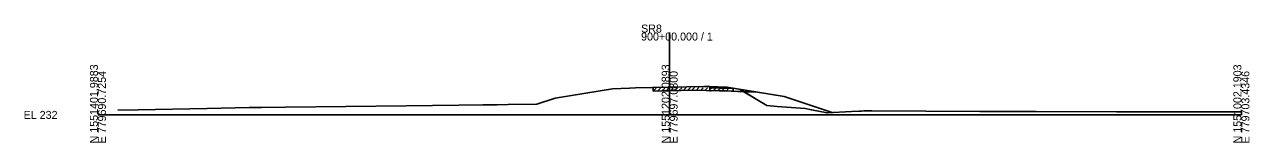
# Model space of a CAD drawing. Extents: x -26 to 787523, y -10 to 1545496.
# Drawn here: x -25.7 to 402.8, y 6490.3 to 6531.7 of the extents above; entities that cross this region are included whole.
import ezdxf

# ---------------------------------------------------------------- set-up
doc = ezdxf.new("R2010")
doc.units = 0
for name, color, linetype in [('50', 7, 'Continuous'), ('XS_CELL', 7, 'Continuous'), ('XS_M_SHAPES_EARTHWORK', 7, 'Continuous'), ('XS_P_FINISHED_GRADE', 7, 'Continuous'), ('XS_P_SUBGRADE_GRANULAR', 7, 'Continuous'), ('XS_X_GROUND', 7, 'Continuous')]:
    doc.layers.add(name, color=color, linetype=linetype)

msp = doc.modelspace()

# ---------------------------------------------------------------- linework, layer by layer
at = {"layer": '50'}
for p, q in [((197.23, 6508.39), (198.26, 6509.41)), ((198.73, 6508.42), (199.76, 6509.44)), ((200.24, 6508.45), (201.26, 6509.48)), ((201.74, 6508.49), (202.76, 6509.51)), ((203.24, 6508.52), (204.26, 6509.54)), ((204.74, 6508.55), (205.76, 6509.57)), ((206.24, 6508.58), (207.26, 6509.6)), ((207.74, 6508.61), (208.73, 6509.6)), ((209.24, 6508.59), (210.22, 6509.57)), ((210.74, 6508.56), (211.72, 6509.54)), ((212.25, 6508.53), (213.23, 6509.51)), ((213.75, 6508.5), (214.73, 6509.48)), ((215.25, 6508.47), (216.23, 6509.45)), ((216.75, 6508.44), (217.73, 6509.42)), ((194.23, 6508.33), (195.25, 6509.35)), ((194.23, 6508.33), (194.23, 6509.33)), ((194.23, 6508.33), (197.61, 6508.4)), ((195.73, 6508.36), (196.75, 6509.38)), ((197.61, 6508.4), (200, 6508.45)), ((200, 6508.45), (208.02, 6508.62)), ((208.02, 6508.62), (217.45, 6508.42)), ((217.45, 6508.42), (222.23, 6508.32)), ((218.25, 6508.4), (219.23, 6509.38)), ((219.75, 6508.37), (220.73, 6509.35)), ((222.23, 6509.32), (222.23, 6508.32))]:
    msp.add_line(p, q, dxfattribs=at)
at = {"layer": 'XS_CELL'}
for p, q in [((200, 6500), (200, 6528.86)), ((0, 6500), (200, 6500)), ((200, 6500), (400, 6500))]:
    msp.add_line(p, q, dxfattribs=at)
at = {"layer": 'XS_M_SHAPES_EARTHWORK'}
for points in [[(224.74, 6508.88), (226, 6508.12), (230.89, 6507.92), (220, 6509.74), (214, 6509.98), (214, 6509.49), (217.45, 6509.42), (222.23, 6509.32)], [(224.74, 6508.88), (226, 6508.12), (230.89, 6507.92), (220, 6509.74), (214, 6509.98), (214, 6509.49), (217.45, 6509.42), (222.23, 6509.32)], [(214, 6508.49), (214, 6509.49), (217.45, 6509.42), (222.23, 6509.32), (222.23, 6508.32), (219.51, 6508.38), (216, 6508.52), (214.37, 6508.49)], [(214, 6508.49), (214, 6509.49), (217.45, 6509.42), (222.23, 6509.32), (222.23, 6508.32), (219.51, 6508.38), (216, 6508.52), (214.37, 6508.49)], [(214, 6508.48), (214, 6508.49), (214.37, 6508.49)], [(214, 6508.48), (214, 6508.49), (214.37, 6508.49)], [(224.74, 6508.88), (226, 6508.12), (219.51, 6508.38), (222.23, 6508.32), (222.23, 6509.32)], [(224.74, 6508.88), (226, 6508.12), (219.51, 6508.38), (222.23, 6508.32), (222.23, 6509.32)], [(237.63, 6502.97), (247.38, 6502.27), (249.66, 6501.81), (255.07, 6500.69), (256.85, 6500.79), (240, 6506.4), (230.89, 6507.92), (226, 6508.12), (230.25, 6505.53), (234, 6503.24)], [(234, 6503.24), (237.63, 6502.97), (247.38, 6502.27), (249.66, 6501.81), (255.07, 6500.69), (256.85, 6500.79), (240, 6506.4), (230.89, 6507.92), (226, 6508.12), (230.25, 6505.53)]]:
    msp.add_lwpolyline(points, close=True, dxfattribs=at)
at = {"layer": 'XS_P_FINISHED_GRADE'}
for p, q in [((214, 6509.98), (220, 6509.74)), ((220, 6509.74), (240, 6506.4)), ((240, 6506.4), (256.85, 6500.79))]:
    msp.add_line(p, q, dxfattribs=at)
at = {"layer": 'XS_P_SUBGRADE_GRANULAR'}
for p, q in [((214, 6508.48), (214, 6509.98)), ((214, 6508.48), (216, 6508.52)), ((216, 6508.52), (230.89, 6507.92))]:
    msp.add_line(p, q, dxfattribs=at)
at = {"layer": 'XS_X_GROUND'}
for p, q in [((180, 6509.18), (186, 6509.42)), ((186, 6509.42), (188, 6509.46)), ((188, 6509.46), (200, 6509.7)), ((200, 6509.7), (212, 6509.94)), ((212, 6509.94), (214, 6509.98)), ((214, 6509.98), (214, 6509.49)), ((214, 6509.49), (217.45, 6509.42)), ((217.45, 6509.42), (222.23, 6509.32)), ((153.59, 6503.71), (160, 6505.84)), ((160, 6505.84), (180, 6509.18)), ((222.23, 6509.32), (224.74, 6508.88)), ((224.74, 6508.88), (230.25, 6505.53)), ((230.25, 6505.53), (234, 6503.24)), ((6.94, 6501.6), (14.05, 6501.75)), ((14.05, 6501.75), (38.21, 6502.25)), ((38.21, 6502.25), (52.95, 6502.55)), ((52.95, 6502.55), (57.27, 6502.64)), ((57.27, 6502.64), (65.6, 6502.72)), ((65.6, 6502.72), (107.77, 6503.12)), ((107.77, 6503.12), (126.22, 6503.36)), ((126.22, 6503.36), (134.7, 6503.47)), ((134.7, 6503.47), (137.11, 6503.5)), ((137.11, 6503.5), (138.26, 6503.51)), ((138.26, 6503.51), (138.92, 6503.52)), ((138.92, 6503.52), (139.36, 6503.53)), ((139.36, 6503.53), (139.67, 6503.53)), ((139.67, 6503.53), (143.52, 6503.6)), ((143.52, 6503.6), (153.59, 6503.71)), ((234, 6503.24), (237.63, 6502.97)), ((237.63, 6502.97), (247.38, 6502.27)), ((247.38, 6502.27), (249.66, 6501.81)), ((249.66, 6501.81), (255.07, 6500.69)), ((255.07, 6500.69), (263.65, 6501.16)), ((263.65, 6501.16), (266.22, 6501.3)), ((266.22, 6501.3), (267.12, 6501.35)), ((267.12, 6501.35), (267.87, 6501.4)), ((267.87, 6501.4), (270.7, 6501.43)), ((270.7, 6501.43), (308.49, 6501.18)), ((308.49, 6501.18), (315.78, 6501.18)), ((315.78, 6501.18), (317.68, 6501.18)), ((317.68, 6501.18), (320.98, 6501.17)), ((320.98, 6501.17), (328.2, 6501.15)), ((328.2, 6501.15), (356.32, 6501.08)), ((356.32, 6501.08), (358.82, 6501.08)), ((358.82, 6501.08), (360.14, 6501.08)), ((360.14, 6501.08), (364.34, 6501.08)), ((364.34, 6501.08), (398.13, 6501.12)), ((398.13, 6501.12), (400, 6501.12))]:
    msp.add_line(p, q, dxfattribs=at)

# ---------------------------------------------------------------- texts
at = {"layer": 'XS_CELL'}
for s, p in [('SR8', (190, 6528.86)), ('900+00.000 / 1', (190, 6526.06)), ('EL 232', (-26, 6498.6))]:
    msp.add_text(s, height=2.8, dxfattribs=at).set_placement(p)
for s, p in [('N 1551401.9883', (0, 6490)), ('E 779690.7254', (2.8, 6490)), ('N 1551202.0893', (200, 6490)), ('E 779697.0800', (202.8, 6490)), ('N 1551002.1903', (400, 6490)), ('E 779703.4346', (402.8, 6490))]:
    msp.add_text(s, height=2.8, rotation=90, dxfattribs=at).set_placement(p)

doc.saveas('drawing.dxf')
